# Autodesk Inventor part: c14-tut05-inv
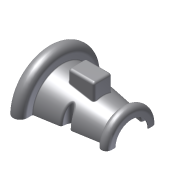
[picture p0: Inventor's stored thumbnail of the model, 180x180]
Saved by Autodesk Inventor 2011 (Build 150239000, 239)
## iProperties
Created: 2010-04
Part Number: c14-tut05-inv
Document SubType Name: Modeling
Designer: CADSoft
Density: 1 g/cm^3
Author: CADSoft
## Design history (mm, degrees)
sketch "Sketch1"
  geometry: L1 (-50, 30)-(-50, 42.5); L2 (-35, 42.5)-(-35, 35); L3 (-35, 35)-(40, 22.5); L4 (40, 22.5)-(40, 25); L5 (50, 25)-(50, 20); L6 (-45.581, 0)-(8.786, 0); A1 r 7.5 centre (-42.5, 42.5) between (-35, 42.5) and (-50, 42.5); A2 r 5 centre (45, 25) between (50, 25) and (40, 25); 2 further points
  constraints: 12 end point, 4 point on circle, 4 tangent, 3 parallel, 2 centre point, 1 coincident, 1 perpendicular, 1 point on line, 1 vertical, 1 other
  dimensions: "d0" = 60 diameter of L1.start L6; "d1" = 85 diameter of L1.end L6; "d2" = 70 diameter of L2.end L6; "d3" = 40 diameter of L5.end L6; "d4" = 45 diameter of L3.end L6; "d5" = 50 diameter of L5.start L6; "d6" = 7.5 radius of A1; "d7" = 5 radius of A2; "d8" = 50 distance from line of L1 point (0, 0); "d9" = 100 distance between parallel lines of L5 L1
feature "RevolutionSrf1" sketch "Sketch1" dims angle "d10" = 180 deg
sketch "Sketch2" dims "d11" = 5, "d12" = 10
  geometry: L1 (-35, 35)-(40, 22.5) reference; L2 (50, -25)-(50, 25) reference; 2 further points; 1 other entity
  constraints: 1 point on line, 2 other
  dimensions: "d13" = 50 distance from line of L2 point (0, 29.167)
extrude_surface "ExtrusionSrf1" sketch "Sketch2" dims "d14" = 30, "d15" = 0
mirror "Mirror1"
feature "Trim1"
feature "Trim2"
feature "Trim3"
feature "Trim4"
workplane "Work Plane1"
sketch "Sketch3"
  geometry: L1 (-15, 10)-(15, 10); L2 (15, 10)-(15, -10); L3 (15, -10)-(-15, -10); L4 (-15, -10)-(-15, 10); 1 further point
  constraints: 8 end point, 2 parallel, 1 horizontal, 1 perpendicular
  dimensions: "d17" = 30 distance of L1.start L1.end; "d18" = 20 distance of L1.end L2.end; "d19" = 15 distance from line of L4 point (0, 0); "d20" = 10 distance from line of L3 point (0, 0)
split "Split1"
delete_face "Delete Face1"
feature "Stitch Surface1"
fillet "Fillet1" dims "d34" = 2
thicken "Thicken1" dims "d35" = 1
body "Solid2"
body "Srf1"
body "Srf2"
body "Srf3"
sketch "3D Sketch1"
  geometry: L1 through (0, 0) direction (1, 5.73e-16) reference; L2 through (0, 0) direction (-1, -5.73e-16) reference; 4 other entities
  constraints: 6 horizontal
body "Srf4"
body "Srf5"
body "Srf6"
extrude_surface "ExtrusionSrf2"
feature "LoftSrf1" dims "d25" = 0, "d26" = 90 deg, "d27" = 0, "d28" = 90 deg
patch "Boundary Patch1" dims "d29" = 0, "d30" = 0, "d31" = 0, "d32" = 0, "d33" = 0
other parameters: "d16" = 45
